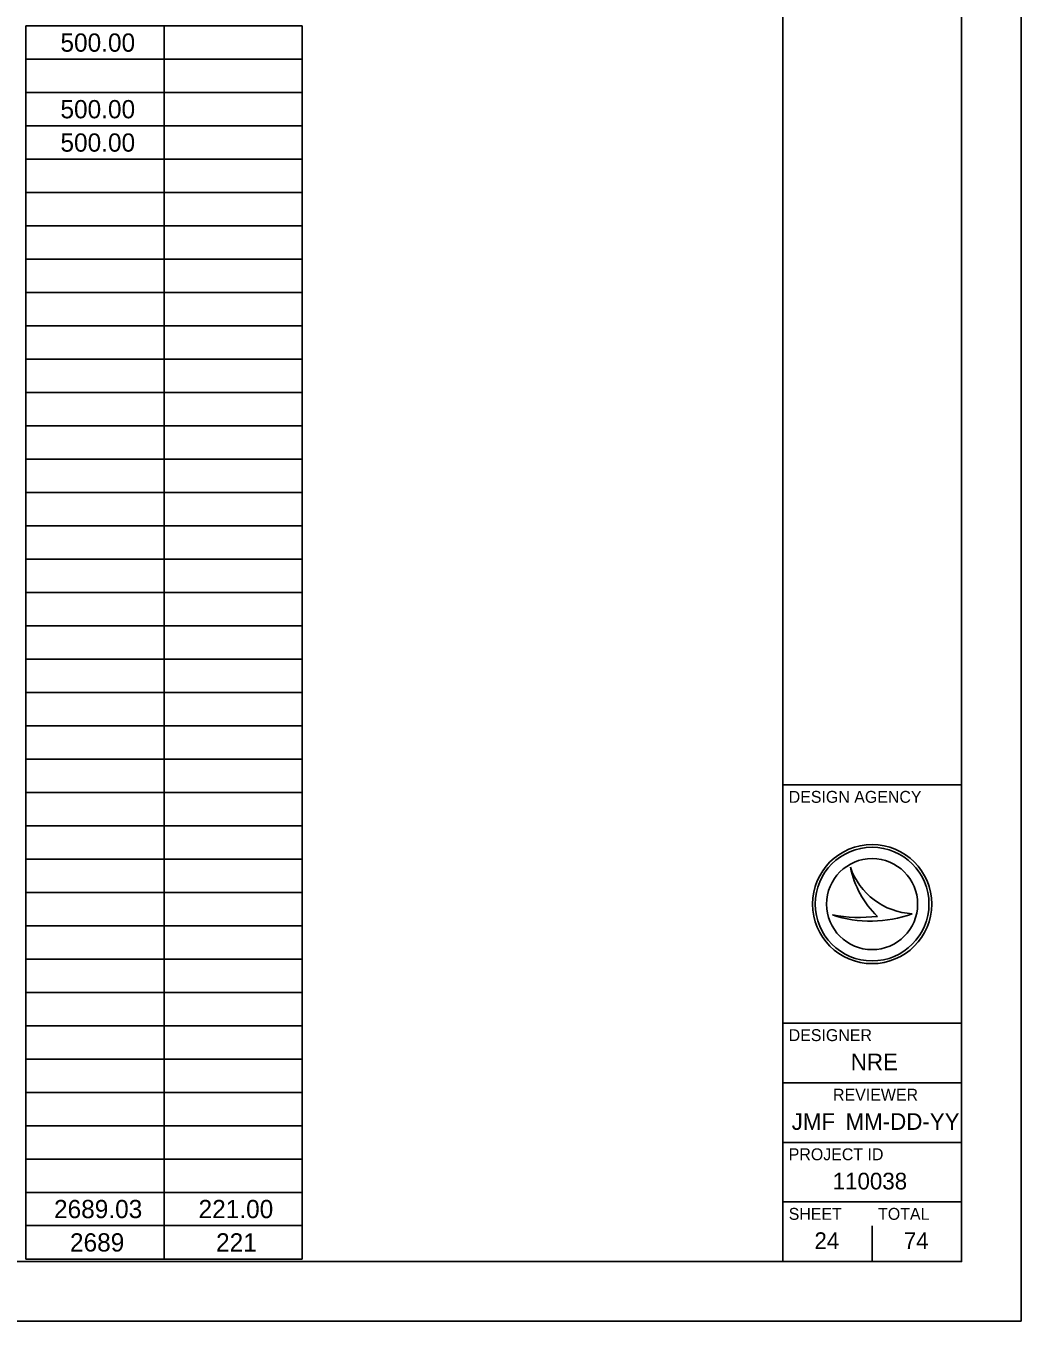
# Model space of a CAD drawing. Extents: x 0 to 34, y 0 to 22.
# Drawn here: x 25.65 to 34, y 0 to 10.87 of the extents above; entities that cross this region are included whole.
import ezdxf

# ---------------------------------------------------------------- set-up
doc = ezdxf.new("R2010")
doc.units = 0
for name, color, linetype in [('SH_Border', 7, 'Continuous'), ('SH_Cut_Line', 7, 'Continuous'), ('SH_Data', 7, 'Continuous'), ('SH_Text', 7, 'Continuous')]:
    doc.layers.add(name, color=color, linetype=linetype)

msp = doc.modelspace()

# ---------------------------------------------------------------- linework, layer by layer
at = {"layer": 'SH_Border'}
for p, q in [((32, 0.5), (32, 21.5)), ((32, 4.5), (33.5, 4.5)), ((32, 2.5), (33.5, 2.5)), ((32, 2), (33.5, 2)), ((32, 1.5), (33.5, 1.5)), ((32, 1), (33.5, 1))]:
    msp.add_line(p, q, dxfattribs=at)
msp.add_lwpolyline([(1.5, 21.5), (33.5, 21.5), (33.5, 0.5), (1.5, 0.5)], close=True, dxfattribs=at)
at = {"layer": 'SH_Cut_Line'}
msp.add_lwpolyline([(0, 0), (34, 0), (34, 22), (0, 22)], close=True, dxfattribs=at)
at = {"layer": 'SH_Data'}
for p, q in [((32.567, 3.81), (32.567, 3.81)), ((32.75, 3.5), (32.75, 3.5)), ((32.417, 3.41), (32.417, 3.41)), ((33.087, 3.419), (33.087, 3.419)), ((32.75, 0.5), (32.75, 0.8)), ((32.375, 0.675), (32.375, 0.675))]:
    msp.add_line(p, q, dxfattribs=at)
for radius in [0.5, 0.477, 0.477, 0.382]:
    msp.add_circle((32.75, 3.5), radius, dxfattribs=at)
for centre, radius, start, end in [((33.116, 3.998), 0.58, 198.9257, 198.9319), ((33.347, 3.97), 0.796, 191.6379, 191.6421), ((33.116, 3.998), 0.58, 198.9319, 267.1657), ((33.347, 3.97), 0.796, 191.6421, 226.0947), ((32.739, 4.37), 1.013, 251.4576, 290.0832), ((32.648, 4.654), 1.266, 259.4964, 259.4995), ((32.739, 4.37), 1.013, 251.4527, 251.4576), ((32.648, 4.654), 1.266, 259.4995, 276.6672)]:
    msp.add_arc(centre, radius, start, end, dxfattribs=at)
at = {"layer": 'SH_Text'}
for p, q in [((25.649, 10.871), (27.967, 10.871)), ((25.649, 10.871), (25.649, 10.591)), ((26.808, 10.871), (26.808, 10.591)), ((27.967, 10.871), (27.967, 10.591)), ((25.649, 10.591), (27.967, 10.591)), ((25.649, 10.591), (25.649, 10.311)), ((26.808, 10.591), (26.808, 10.311)), ((27.967, 10.591), (27.967, 10.311)), ((25.649, 10.311), (27.967, 10.311)), ((25.649, 10.311), (25.649, 10.031)), ((26.808, 10.311), (26.808, 10.031)), ((27.967, 10.311), (27.967, 10.031)), ((25.649, 10.031), (27.967, 10.031)), ((25.649, 10.031), (25.649, 9.752)), ((26.808, 10.031), (26.808, 9.752)), ((27.967, 10.031), (27.967, 9.752)), ((25.649, 9.752), (27.967, 9.752)), ((25.649, 9.752), (25.649, 9.472)), ((26.808, 9.752), (26.808, 9.472)), ((27.967, 9.752), (27.967, 9.472)), ((25.649, 9.472), (27.967, 9.472)), ((25.649, 9.472), (25.649, 9.192)), ((26.808, 9.472), (26.808, 9.192)), ((27.967, 9.472), (27.967, 9.192)), ((25.649, 9.192), (27.967, 9.192)), ((25.649, 9.192), (25.649, 8.913)), ((26.808, 9.192), (26.808, 8.913)), ((27.967, 9.192), (27.967, 8.913)), ((25.649, 8.913), (27.967, 8.913)), ((25.649, 8.913), (25.649, 8.633)), ((26.808, 8.913), (26.808, 8.633)), ((27.967, 8.913), (27.967, 8.633)), ((25.649, 8.633), (27.967, 8.633)), ((25.649, 8.633), (25.649, 8.353)), ((26.808, 8.633), (26.808, 8.353)), ((27.967, 8.633), (27.967, 8.353)), ((25.649, 8.353), (27.967, 8.353)), ((25.649, 8.353), (25.649, 8.073)), ((26.808, 8.353), (26.808, 8.073)), ((27.967, 8.353), (27.967, 8.073)), ((25.649, 8.073), (27.967, 8.073)), ((25.649, 8.073), (25.649, 7.794)), ((26.808, 8.073), (26.808, 7.794)), ((27.967, 8.073), (27.967, 7.794)), ((25.649, 7.794), (27.967, 7.794)), ((25.649, 7.794), (25.649, 7.514)), ((26.808, 7.794), (26.808, 7.514)), ((27.967, 7.794), (27.967, 7.514)), ((25.649, 7.514), (27.967, 7.514)), ((25.649, 7.514), (25.649, 7.234)), ((26.808, 7.514), (26.808, 7.234)), ((27.967, 7.514), (27.967, 7.234)), ((25.649, 7.234), (27.967, 7.234)), ((25.649, 7.234), (25.649, 6.955)), ((26.808, 7.234), (26.808, 6.955)), ((27.967, 7.234), (27.967, 6.955)), ((25.649, 6.955), (27.967, 6.955)), ((25.649, 6.955), (25.649, 6.675)), ((26.808, 6.955), (26.808, 6.675)), ((27.967, 6.955), (27.967, 6.675)), ((25.649, 6.675), (27.967, 6.675)), ((25.649, 6.675), (25.649, 6.395)), ((26.808, 6.675), (26.808, 6.395)), ((27.967, 6.675), (27.967, 6.395)), ((25.649, 6.395), (27.967, 6.395)), ((25.649, 6.395), (25.649, 6.115)), ((26.808, 6.395), (26.808, 6.115)), ((27.967, 6.395), (27.967, 6.115)), ((25.649, 6.115), (27.967, 6.115)), ((25.649, 6.115), (25.649, 5.836)), ((26.808, 6.115), (26.808, 5.836)), ((27.967, 6.115), (27.967, 5.836)), ((25.649, 5.836), (27.967, 5.836)), ((25.649, 5.836), (25.649, 5.276)), ((26.808, 5.836), (26.808, 5.276)), ((27.967, 5.836), (27.967, 5.276)), ((25.649, 5.556), (27.967, 5.556)), ((25.649, 5.276), (27.967, 5.276)), ((25.649, 5.276), (25.649, 4.997)), ((26.808, 5.276), (26.808, 4.997)), ((27.967, 5.276), (27.967, 4.997)), ((25.649, 4.997), (27.967, 4.997)), ((25.649, 4.997), (25.649, 4.717)), ((26.808, 4.997), (26.808, 4.717)), ((27.967, 4.997), (27.967, 4.717)), ((25.649, 4.717), (27.967, 4.717)), ((25.649, 4.717), (25.649, 4.437)), ((26.808, 4.717), (26.808, 4.437)), ((27.967, 4.717), (27.967, 4.437)), ((25.649, 4.437), (27.967, 4.437)), ((25.649, 4.437), (25.649, 3.878)), ((26.808, 4.437), (26.808, 3.878)), ((27.967, 4.437), (27.967, 3.878)), ((25.649, 4.157), (27.967, 4.157)), ((25.649, 3.878), (27.967, 3.878)), ((25.649, 3.878), (25.649, 3.598)), ((26.808, 3.878), (26.808, 3.598)), ((27.967, 3.878), (27.967, 3.598)), ((25.649, 3.598), (27.967, 3.598)), ((25.649, 3.598), (25.649, 3.318)), ((26.808, 3.598), (26.808, 3.318)), ((27.967, 3.598), (27.967, 3.318)), ((25.649, 3.318), (27.967, 3.318)), ((25.649, 3.318), (25.649, 3.038)), ((26.808, 3.318), (26.808, 3.038)), ((27.967, 3.318), (27.967, 3.038)), ((25.649, 3.038), (27.967, 3.038)), ((25.649, 3.038), (25.649, 2.479)), ((26.808, 3.038), (26.808, 2.479)), ((27.967, 3.038), (27.967, 2.479)), ((25.649, 2.759), (27.967, 2.759)), ((25.649, 2.479), (27.967, 2.479)), ((25.649, 2.479), (25.649, 2.199)), ((26.808, 2.479), (26.808, 2.199)), ((27.967, 2.479), (27.967, 2.199)), ((25.649, 2.199), (27.967, 2.199)), ((25.649, 2.199), (25.649, 1.92)), ((26.808, 2.199), (26.808, 1.92)), ((27.967, 2.199), (27.967, 1.92)), ((25.649, 1.92), (27.967, 1.92)), ((25.649, 1.92), (25.649, 1.64)), ((26.808, 1.92), (26.808, 1.64)), ((27.967, 1.92), (27.967, 1.64)), ((25.649, 1.64), (27.967, 1.64)), ((25.649, 1.64), (25.649, 1.08)), ((26.808, 1.64), (26.808, 1.08)), ((27.967, 1.64), (27.967, 1.08)), ((25.649, 1.36), (27.967, 1.36)), ((25.649, 1.08), (27.967, 1.08)), ((25.649, 1.08), (25.649, 0.801)), ((26.808, 1.08), (26.808, 0.801)), ((27.967, 1.08), (27.967, 0.801)), ((25.649, 0.801), (27.967, 0.801)), ((25.649, 0.801), (25.649, 0.521)), ((26.808, 0.801), (26.808, 0.521)), ((27.967, 0.801), (27.967, 0.521)), ((25.649, 0.521), (27.967, 0.521))]:
    msp.add_line(p, q, dxfattribs=at)

# ---------------------------------------------------------------- texts
at = {"layer": 'SH_Data'}
for s, height, p in [('DESIGN AGENCY', 0.1, (32.05, 4.35)), ('DESIGNER', 0.1, (32.05, 2.35)), ('NRE', 0.14, (32.571, 2.105)), ('REVIEWER', 0.1, (32.422, 1.85)), ('JMF', 0.14, (32.075, 1.605)), ('MM-DD-YY', 0.14, (32.527, 1.605)), ('PROJECT ID', 0.1, (32.05, 1.35)), ('110038', 0.14, (32.419, 1.105)), ('SHEET', 0.1, (32.05, 0.85)), ('TOTAL', 0.1, (32.8, 0.85)), ('24', 0.14, (32.266, 0.605)), ('74', 0.14, (33.016, 0.605))]:
    msp.add_text(s, height=height, dxfattribs=at).set_placement(p)
at = {"layer": 'SH_Text'}
for s, p in [('500.00', (25.939, 10.654)), ('500.00', (25.939, 10.095)), ('500.00', (25.939, 9.815)), ('2689.03', (25.885, 0.864)), ('221.00', (27.098, 0.864)), ('2689', (26.019, 0.584)), ('221', (27.245, 0.584))]:
    msp.add_text(s, height=0.1532, dxfattribs=at).set_placement(p)

doc.saveas('drawing.dxf')
